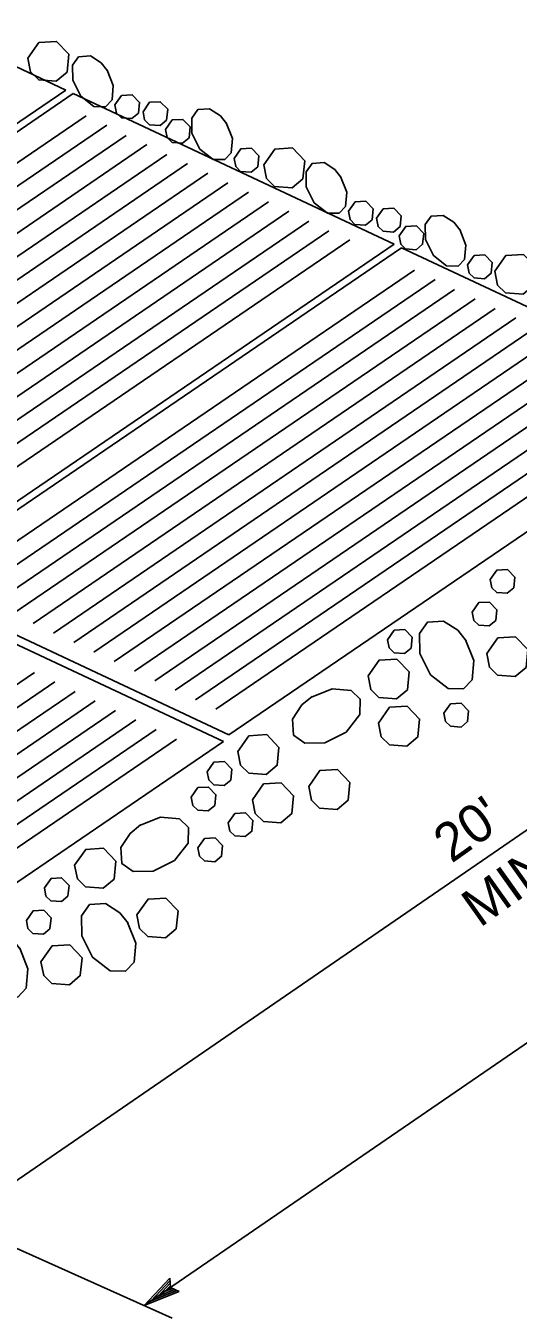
# Model space of a CAD drawing. Extents: x 6709491 to 6710959, y 1869789 to 1870763.
# Drawn here: x 6709966.5 to 6710043.7, y 1870116.6 to 1870319.2 of the extents above; entities that cross this region are included whole.
import ezdxf

# ---------------------------------------------------------------- set-up
doc = ezdxf.new("R2010")
doc.units = 0
for name, color, linetype in [('56 Stg 3 Anno', 7, 'Continuous'), ('57 Undefined', 7, 'Continuous'), ('60 Nongeo Data', 7, 'Continuous')]:
    doc.layers.add(name, color=color, linetype=linetype)

msp = doc.modelspace()

# ---------------------------------------------------------------- linework, layer by layer
at = {"layer": '56 Stg 3 Anno'}
for p, q in [((6709960.88, 1870135.33), (6710117.29, 1870242.71)), ((6709985.07, 1870118.55), (6710151.91, 1870233.1)), ((6709932.78, 1870142.01), (6709989.45, 1870116.59)), ((6709985.07, 1870118.55), (6709989.1, 1870122.86)), ((6709986.17, 1870119.31), (6709989.1, 1870122.45)), ((6709987.26, 1870120.05), (6709989.15, 1870122.08)), ((6709988.35, 1870120.8), (6709989.16, 1870121.67)), ((6709989.1, 1870122.86), (6709989.1, 1870122.86)), ((6709989.1, 1870122.86), (6709989.18, 1870121.38)), ((6709990.55, 1870120.75), (6709985.07, 1870118.55)), ((6709990.18, 1870120.92), (6709986.16, 1870119.3)), ((6709989.8, 1870121.07), (6709987.26, 1870120.05)), ((6709989.47, 1870121.25), (6709988.35, 1870120.8)), ((6709989.18, 1870121.38), (6709990.55, 1870120.75)), ((6709990.55, 1870120.75), (6709990.55, 1870120.75)), ((6709985.07, 1870118.55), (6709985.07, 1870118.55))]:
    msp.add_line(p, q, dxfattribs=at)
msp.add_lwpolyline([(6710040.02, 1870280.7), (6710041.76, 1870283.17), (6710044.53, 1870283.33), (6710046.46, 1870281.33), (6710046.18, 1870278.52), (6710044.47, 1870277.1), (6710041.73, 1870277.3), (6710040.44, 1870278.55), (6710040.02, 1870280.7)], dxfattribs=at)
at = {"layer": '60 Nongeo Data'}
for p, q in [((6709933.89, 1870327.37), (6709972.77, 1870309.11)), ((6709895.36, 1870256.35), (6709972.77, 1870309.11)), ((6709896.53, 1870255.81), (6709973.94, 1870308.57)), ((6709973.94, 1870308.57), (6710024.25, 1870284.94)), ((6709903.43, 1870255.63), (6709975.95, 1870305.05)), ((6709906.61, 1870254.14), (6709979.18, 1870303.59)), ((6709909.79, 1870252.64), (6709982.23, 1870302.01)), ((6709912.98, 1870251.15), (6709985.49, 1870300.57)), ((6709916.16, 1870249.65), (6709988.6, 1870299.03)), ((6709919.34, 1870248.16), (6709991.87, 1870297.59)), ((6709922.52, 1870246.67), (6709995.05, 1870296.1)), ((6709925.7, 1870245.17), (6709998.17, 1870294.57)), ((6709928.88, 1870243.68), (6710001.39, 1870293.1)), ((6709932.06, 1870242.19), (6710004.53, 1870291.58)), ((6709935.24, 1870240.69), (6710007.74, 1870290.1)), ((6709938.43, 1870239.2), (6710010.88, 1870288.58)), ((6709941.61, 1870237.7), (6710013.99, 1870287.04)), ((6709944.79, 1870236.21), (6710017.28, 1870285.62)), ((6709946.84, 1870232.18), (6710024.25, 1870284.94)), ((6709948.01, 1870231.63), (6710025.41, 1870284.39)), ((6710025.41, 1870284.39), (6710075.72, 1870260.77)), ((6709954.91, 1870231.46), (6710027.42, 1870280.88)), ((6709958.09, 1870229.96), (6710030.66, 1870279.42)), ((6709961.27, 1870228.47), (6710033.7, 1870277.84)), ((6709964.45, 1870226.98), (6710036.97, 1870276.4)), ((6709967.63, 1870225.48), (6710040.08, 1870274.86)), ((6709970.82, 1870223.99), (6710043.34, 1870273.42)), ((6709974, 1870222.49), (6710046.53, 1870271.93)), ((6709977.18, 1870221), (6710049.65, 1870270.4)), ((6709980.36, 1870219.51), (6710052.87, 1870268.93)), ((6709983.54, 1870218.01), (6710056.01, 1870267.4)), ((6709986.72, 1870216.52), (6710059.22, 1870265.93)), ((6709989.9, 1870215.03), (6710062.35, 1870264.41)), ((6709993.08, 1870213.53), (6710065.47, 1870262.87)), ((6709996.27, 1870212.04), (6710068.76, 1870261.45)), ((6709998.31, 1870208.01), (6710075.72, 1870260.77)), ((6709948.01, 1870231.63), (6709998.31, 1870208.01)), ((6709947.18, 1870230.6), (6709997.49, 1870206.98)), ((6709895.17, 1870168.3), (6709967.84, 1870217.83)), ((6709898.35, 1870166.8), (6709971.02, 1870216.34)), ((6709901.53, 1870165.31), (6709974.21, 1870214.84)), ((6709904.71, 1870163.82), (6709977.39, 1870213.35)), ((6709907.89, 1870162.32), (6709980.57, 1870211.86)), ((6709911.07, 1870160.83), (6709983.75, 1870210.36)), ((6709914.25, 1870159.33), (6709986.93, 1870208.87)), ((6709917.44, 1870157.84), (6709990.11, 1870207.37)), ((6709919.56, 1870153.86), (6709997.49, 1870206.98))]:
    msp.add_line(p, q, dxfattribs=at)
for points in [[(6709966.8, 1870314.1), (6709968.54, 1870316.57), (6709971.31, 1870316.73), (6709973.24, 1870314.73), (6709972.96, 1870311.92), (6709971.25, 1870310.5), (6709968.51, 1870310.7), (6709967.22, 1870311.95), (6709966.8, 1870314.1)], [(6709979.24, 1870312.24), (6709980.21, 1870309.8), (6709980.01, 1870307.56), (6709979, 1870306.49), (6709977.18, 1870306.52), (6709975.11, 1870308.14), (6709973.86, 1870310.64), (6709973.82, 1870313), (6709974.76, 1870314.32), (6709976.64, 1870314.45), (6709978.32, 1870313.37), (6709979.3, 1870312.14)], [(6709980.47, 1870306.8), (6709981.51, 1870308.28), (6709983.18, 1870308.37), (6709984.34, 1870307.17), (6709984.17, 1870305.49), (6709983.14, 1870304.64), (6709981.5, 1870304.75), (6709980.72, 1870305.5), (6709980.47, 1870306.8)], [(6709984.87, 1870305.71), (6709985.91, 1870307.19), (6709987.58, 1870307.29), (6709988.74, 1870306.09), (6709988.57, 1870304.4), (6709987.54, 1870303.55), (6709985.9, 1870303.67), (6709985.12, 1870304.42), (6709984.87, 1870305.71)], [(6709997.92, 1870303.95), (6709998.88, 1870301.51), (6709998.69, 1870299.27), (6709997.68, 1870298.21), (6709995.86, 1870298.24), (6709993.79, 1870299.86), (6709992.54, 1870302.36), (6709992.5, 1870304.71), (6709993.44, 1870306.04), (6709995.32, 1870306.16), (6709997, 1870305.09), (6709997.98, 1870303.86)], [(6709988.41, 1870302.94), (6709989.46, 1870304.43), (6709991.12, 1870304.52), (6709992.28, 1870303.32), (6709992.11, 1870301.64), (6709991.08, 1870300.78), (6709989.44, 1870300.9), (6709988.67, 1870301.65), (6709988.41, 1870302.94)], [(6709999.15, 1870298.4), (6710000.19, 1870299.89), (6710001.86, 1870299.98), (6710003.02, 1870298.78), (6710002.85, 1870297.1), (6710001.82, 1870296.24), (6710000.18, 1870296.36), (6709999.4, 1870297.11), (6709999.15, 1870298.4)], [(6710003.79, 1870297.4), (6710005.53, 1870299.87), (6710008.3, 1870300.03), (6710010.23, 1870298.03), (6710009.95, 1870295.22), (6710008.24, 1870293.8), (6710005.5, 1870294), (6710004.21, 1870295.25), (6710003.79, 1870297.4)], [(6710015.85, 1870295.54), (6710016.82, 1870293.1), (6710016.62, 1870290.86), (6710015.61, 1870289.79), (6710013.79, 1870289.82), (6710011.72, 1870291.44), (6710010.47, 1870293.94), (6710010.43, 1870296.3), (6710011.37, 1870297.62), (6710013.25, 1870297.75), (6710014.93, 1870296.67), (6710015.91, 1870295.44)], [(6710017.08, 1870290.1), (6710018.12, 1870291.58), (6710019.79, 1870291.67), (6710020.95, 1870290.47), (6710020.78, 1870288.79), (6710019.75, 1870287.94), (6710018.11, 1870288.05), (6710017.33, 1870288.8), (6710017.08, 1870290.1)], [(6710021.48, 1870289.01), (6710022.53, 1870290.49), (6710024.19, 1870290.59), (6710025.35, 1870289.39), (6710025.18, 1870287.7), (6710024.15, 1870286.85), (6710022.51, 1870286.97), (6710021.73, 1870287.72), (6710021.48, 1870289.01)], [(6710025.02, 1870286.24), (6710026.07, 1870287.73), (6710027.73, 1870287.82), (6710028.89, 1870286.62), (6710028.72, 1870284.94), (6710027.69, 1870284.08), (6710026.05, 1870284.2), (6710025.28, 1870284.95), (6710025.02, 1870286.24)], [(6710034.53, 1870287.25), (6710035.5, 1870284.81), (6710035.3, 1870282.57), (6710034.29, 1870281.51), (6710032.47, 1870281.54), (6710030.4, 1870283.16), (6710029.15, 1870285.66), (6710029.11, 1870288.01), (6710030.05, 1870289.34), (6710031.93, 1870289.46), (6710033.61, 1870288.39), (6710034.59, 1870287.16)], [(6710035.76, 1870281.7), (6710036.8, 1870283.19), (6710038.47, 1870283.28), (6710039.63, 1870282.08), (6710039.46, 1870280.4), (6710038.43, 1870279.54), (6710036.79, 1870279.66), (6710036.01, 1870280.41), (6710035.76, 1870281.7)], [(6710039.3, 1870232.38), (6710040.34, 1870233.87), (6710042.01, 1870233.96), (6710043.17, 1870232.76), (6710043, 1870231.08), (6710041.97, 1870230.22), (6710040.33, 1870230.34), (6710039.55, 1870231.09), (6710039.3, 1870232.38)], [(6710036.48, 1870227.27), (6710037.53, 1870228.76), (6710039.19, 1870228.85), (6710040.35, 1870227.65), (6710040.18, 1870225.97), (6710039.15, 1870225.11), (6710037.51, 1870225.23), (6710036.73, 1870225.98), (6710036.48, 1870227.27)], [(6710035.45, 1870222.91), (6710036.74, 1870219.66), (6710036.48, 1870216.67), (6710035.13, 1870215.25), (6710032.7, 1870215.29), (6710029.95, 1870217.45), (6710028.28, 1870220.78), (6710028.22, 1870223.92), (6710029.48, 1870225.69), (6710031.98, 1870225.86), (6710034.22, 1870224.42), (6710035.53, 1870222.78)], [(6710023.22, 1870222.95), (6710024.27, 1870224.43), (6710025.93, 1870224.53), (6710027.09, 1870223.33), (6710026.92, 1870221.64), (6710025.89, 1870220.79), (6710024.25, 1870220.91), (6710023.48, 1870221.66), (6710023.22, 1870222.95)], [(6710038.77, 1870220.78), (6710040.51, 1870223.26), (6710043.28, 1870223.42), (6710045.22, 1870221.41), (6710044.94, 1870218.61), (6710043.22, 1870217.18), (6710040.48, 1870217.38), (6710039.19, 1870218.63), (6710038.77, 1870220.78)], [(6710020.15, 1870217.28), (6710021.89, 1870219.76), (6710024.67, 1870219.92), (6710026.6, 1870217.91), (6710026.32, 1870215.11), (6710024.6, 1870213.68), (6710021.86, 1870213.88), (6710020.57, 1870215.13), (6710020.15, 1870217.28)], [(6710011.27, 1870213.96), (6710014.52, 1870215.25), (6710017.51, 1870214.99), (6710018.93, 1870213.64), (6710018.89, 1870211.22), (6710016.73, 1870208.46), (6710013.4, 1870206.79), (6710010.26, 1870206.74), (6710008.49, 1870207.99), (6710008.32, 1870210.5), (6710009.76, 1870212.73), (6710011.4, 1870214.04)], [(6710032.06, 1870211.41), (6710033.11, 1870212.89), (6710034.77, 1870212.99), (6710035.93, 1870211.78), (6710035.76, 1870210.1), (6710034.74, 1870209.25), (6710033.09, 1870209.37), (6710032.31, 1870210.12), (6710032.06, 1870211.41)], [(6710021.79, 1870209.88), (6710023.53, 1870212.35), (6710026.3, 1870212.51), (6710028.23, 1870210.51), (6710027.95, 1870207.7), (6710026.24, 1870206.28), (6710023.5, 1870206.47), (6710022.21, 1870207.73), (6710021.79, 1870209.88)], [(6709999.74, 1870205.43), (6710001.48, 1870207.9), (6710004.26, 1870208.06), (6710006.19, 1870206.06), (6710005.91, 1870203.26), (6710004.2, 1870201.83), (6710001.45, 1870202.03), (6710000.16, 1870203.28), (6709999.75, 1870205.43)], [(6709994.92, 1870202.25), (6709995.96, 1870203.74), (6709997.63, 1870203.84), (6709998.79, 1870202.63), (6709998.62, 1870200.95), (6709997.59, 1870200.09), (6709995.95, 1870200.21), (6709995.17, 1870200.97), (6709994.92, 1870202.25)], [(6710010.85, 1870199.95), (6710012.59, 1870202.42), (6710015.37, 1870202.58), (6710017.3, 1870200.58), (6710017.02, 1870197.77), (6710015.31, 1870196.35), (6710012.56, 1870196.54), (6710011.27, 1870197.79), (6710010.86, 1870199.95)], [(6709992.43, 1870198.27), (6709993.47, 1870199.75), (6709995.14, 1870199.85), (6709996.3, 1870198.65), (6709996.13, 1870196.96), (6709995.1, 1870196.11), (6709993.45, 1870196.23), (6709992.68, 1870196.98), (6709992.43, 1870198.27)], [(6710002.03, 1870197.85), (6710003.77, 1870200.33), (6710006.55, 1870200.49), (6710008.48, 1870198.48), (6710008.2, 1870195.68), (6710006.49, 1870194.25), (6710003.74, 1870194.45), (6710002.45, 1870195.7), (6710002.03, 1870197.85)], [(6709984.34, 1870193.82), (6709987.59, 1870195.11), (6709990.58, 1870194.85), (6709992, 1870193.5), (6709991.96, 1870191.07), (6709989.8, 1870188.32), (6709986.47, 1870186.65), (6709983.33, 1870186.59), (6709981.56, 1870187.85), (6709981.39, 1870190.35), (6709982.83, 1870192.59), (6709984.47, 1870193.9)], [(6709998.24, 1870194.23), (6709999.29, 1870195.72), (6710000.95, 1870195.81), (6710002.11, 1870194.61), (6710001.94, 1870192.93), (6710000.91, 1870192.07), (6709999.27, 1870192.19), (6709998.49, 1870192.94), (6709998.24, 1870194.23)], [(6709993.47, 1870190.3), (6709994.52, 1870191.78), (6709996.18, 1870191.88), (6709997.34, 1870190.68), (6709997.18, 1870188.99), (6709996.15, 1870188.14), (6709994.5, 1870188.26), (6709993.73, 1870189.01), (6709993.48, 1870190.3)], [(6709974.15, 1870187.6), (6709975.89, 1870190.08), (6709978.66, 1870190.24), (6709980.6, 1870188.23), (6709980.32, 1870185.43), (6709978.6, 1870184), (6709975.86, 1870184.2), (6709974.57, 1870185.45), (6709974.15, 1870187.6)], [(6709969.4, 1870184.05), (6709970.44, 1870185.53), (6709972.11, 1870185.63), (6709973.27, 1870184.43), (6709973.1, 1870182.75), (6709972.07, 1870181.89), (6709970.42, 1870182.01), (6709969.65, 1870182.76), (6709969.4, 1870184.05)], [(6709983.92, 1870179.8), (6709985.66, 1870182.28), (6709988.44, 1870182.43), (6709990.37, 1870180.43), (6709990.09, 1870177.63), (6709988.38, 1870176.2), (6709985.63, 1870176.4), (6709984.34, 1870177.65), (6709983.92, 1870179.8)], [(6709966.58, 1870178.94), (6709967.62, 1870180.43), (6709969.29, 1870180.52), (6709970.45, 1870179.32), (6709970.28, 1870177.64), (6709969.25, 1870176.78), (6709967.61, 1870176.9), (6709966.83, 1870177.65), (6709966.58, 1870178.94)], [(6709982.45, 1870178.63), (6709983.74, 1870175.38), (6709983.48, 1870172.39), (6709982.13, 1870170.97), (6709979.71, 1870171.01), (6709976.95, 1870173.17), (6709975.28, 1870176.5), (6709975.23, 1870179.64), (6709976.48, 1870181.41), (6709978.99, 1870181.58), (6709981.22, 1870180.14), (6709982.53, 1870178.5)], [(6709965.54, 1870174.58), (6709966.83, 1870171.33), (6709966.57, 1870168.34), (6709965.22, 1870166.92), (6709962.8, 1870166.96), (6709960.04, 1870169.12), (6709958.38, 1870172.45), (6709958.32, 1870175.59), (6709959.58, 1870177.36), (6709962.08, 1870177.53), (6709964.32, 1870176.09), (6709965.63, 1870174.45)], [(6709968.87, 1870172.45), (6709970.61, 1870174.93), (6709973.38, 1870175.09), (6709975.31, 1870173.08), (6709975.03, 1870170.28), (6709973.32, 1870168.85), (6709970.58, 1870169.05), (6709969.29, 1870170.3), (6709968.87, 1870172.45)]]:
    msp.add_lwpolyline(points, dxfattribs=at)

# ---------------------------------------------------------------- texts
at = {"layer": '57 Undefined'}
for s, p in [("20'", (6710033.25, 1870187.8)), ('MIN', (6710037.7, 1870177.72))]:
    msp.add_text(s, height=6, rotation=35.4657, dxfattribs=at).set_placement(p)

doc.saveas('drawing.dxf')
